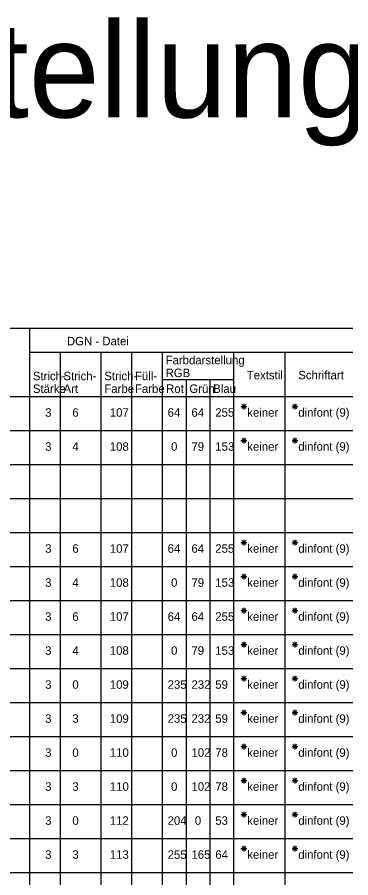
# Model space of a CAD drawing. Extents: x -14.3 to 23.8, y -56.3 to 8.
# Drawn here: x 11.07 to 15.97, y -8.08 to 4.57 of the extents above; entities that cross this region are included whole.
import ezdxf

# ---------------------------------------------------------------- set-up
doc = ezdxf.new("R2010")
doc.units = 0
doc.layers.add('Default', color=7, linetype='Continuous')

msp = doc.modelspace()

# ---------------------------------------------------------------- linework, layer by layer
at = {"layer": 'Default'}
for p, q in [((0, 0), (16, 0)), ((11.25, 0), (11.25, -53.5)), ((11.25, -0.35), (16, -0.35)), ((11.7, -0.35), (11.7, -44.5)), ((12.3, -0.35), (12.3, -44.5)), ((12.75, -0.35), (12.75, -44.5)), ((13.2, -0.35), (13.2, -44.5)), ((14.25, -0.35), (14.25, -48)), ((15, -0.35), (15, -48)), ((13.2, -0.75), (14.25, -0.75)), ((13.55, -0.75), (13.55, -44.5)), ((13.9, -0.75), (13.9, -44.5)), ((0, -1), (14.169, -1)), ((0, -1), (16, -1)), ((14.37, -1.12), (14.43, -1.18)), ((14.43, -1.12), (14.37, -1.18)), ((14.4, -1.108), (14.4, -1.192)), ((15.12, -1.12), (15.18, -1.18)), ((15.18, -1.12), (15.12, -1.18)), ((15.15, -1.108), (15.15, -1.192)), ((14.358, -1.15), (14.442, -1.15)), ((15.108, -1.15), (15.192, -1.15)), ((0, -1.5), (16, -1.5)), ((14.37, -1.62), (14.43, -1.68)), ((14.43, -1.62), (14.37, -1.68)), ((14.4, -1.608), (14.4, -1.692)), ((15.12, -1.62), (15.18, -1.68)), ((15.18, -1.62), (15.12, -1.68)), ((15.15, -1.608), (15.15, -1.692)), ((14.358, -1.65), (14.442, -1.65)), ((15.108, -1.65), (15.192, -1.65)), ((0, -2), (16, -2)), ((0, -2.5), (16, -2.5)), ((0, -3), (16, -3)), ((14.358, -3.15), (14.442, -3.15)), ((14.37, -3.12), (14.43, -3.18)), ((14.43, -3.12), (14.37, -3.18)), ((14.4, -3.108), (14.4, -3.192)), ((15.108, -3.15), (15.192, -3.15)), ((15.12, -3.12), (15.18, -3.18)), ((15.18, -3.12), (15.12, -3.18)), ((15.15, -3.108), (15.15, -3.192)), ((0, -3.5), (16, -3.5)), ((14.358, -3.65), (14.442, -3.65)), ((14.37, -3.62), (14.43, -3.68)), ((14.43, -3.62), (14.37, -3.68)), ((14.4, -3.608), (14.4, -3.692)), ((15.108, -3.65), (15.192, -3.65)), ((15.12, -3.62), (15.18, -3.68)), ((15.18, -3.62), (15.12, -3.68)), ((15.15, -3.608), (15.15, -3.692)), ((0, -4), (16, -4)), ((14.358, -4.15), (14.442, -4.15)), ((14.37, -4.12), (14.43, -4.18)), ((14.43, -4.12), (14.37, -4.18)), ((14.4, -4.108), (14.4, -4.192)), ((15.108, -4.15), (15.192, -4.15)), ((15.12, -4.12), (15.18, -4.18)), ((15.18, -4.12), (15.12, -4.18)), ((15.15, -4.108), (15.15, -4.192)), ((0, -4.5), (16, -4.5)), ((14.358, -4.65), (14.442, -4.65)), ((14.37, -4.62), (14.43, -4.68)), ((14.43, -4.62), (14.37, -4.68)), ((14.4, -4.608), (14.4, -4.692)), ((15.108, -4.65), (15.192, -4.65)), ((15.12, -4.62), (15.18, -4.68)), ((15.18, -4.62), (15.12, -4.68)), ((15.15, -4.608), (15.15, -4.692)), ((0, -5), (16, -5)), ((14.358, -5.15), (14.442, -5.15)), ((14.37, -5.12), (14.43, -5.18)), ((14.43, -5.12), (14.37, -5.18)), ((14.4, -5.108), (14.4, -5.192)), ((15.108, -5.15), (15.192, -5.15)), ((15.12, -5.12), (15.18, -5.18)), ((15.18, -5.12), (15.12, -5.18)), ((15.15, -5.108), (15.15, -5.192)), ((0, -5.5), (16, -5.5)), ((14.358, -5.65), (14.442, -5.65)), ((14.37, -5.62), (14.43, -5.68)), ((14.43, -5.62), (14.37, -5.68)), ((14.4, -5.608), (14.4, -5.692)), ((15.108, -5.65), (15.192, -5.65)), ((15.12, -5.62), (15.18, -5.68)), ((15.18, -5.62), (15.12, -5.68)), ((15.15, -5.608), (15.15, -5.692)), ((0, -6), (16, -6)), ((14.358, -6.15), (14.442, -6.15)), ((14.37, -6.12), (14.43, -6.18)), ((14.43, -6.12), (14.37, -6.18)), ((14.4, -6.108), (14.4, -6.192)), ((15.108, -6.15), (15.192, -6.15)), ((15.12, -6.12), (15.18, -6.18)), ((15.18, -6.12), (15.12, -6.18)), ((15.15, -6.108), (15.15, -6.192)), ((0, -6.5), (16, -6.5)), ((14.358, -6.65), (14.442, -6.65)), ((14.37, -6.62), (14.43, -6.68)), ((14.43, -6.62), (14.37, -6.68)), ((14.4, -6.608), (14.4, -6.692)), ((15.108, -6.65), (15.192, -6.65)), ((15.12, -6.62), (15.18, -6.68)), ((15.18, -6.62), (15.12, -6.68)), ((15.15, -6.608), (15.15, -6.692)), ((0, -7), (16, -7)), ((14.358, -7.15), (14.442, -7.15)), ((14.37, -7.12), (14.43, -7.18)), ((14.43, -7.12), (14.37, -7.18)), ((14.4, -7.108), (14.4, -7.192)), ((15.108, -7.15), (15.192, -7.15)), ((15.12, -7.12), (15.18, -7.18)), ((15.18, -7.12), (15.12, -7.18)), ((15.15, -7.108), (15.15, -7.192)), ((0, -7.5), (16, -7.5)), ((14.358, -7.65), (14.442, -7.65)), ((14.37, -7.62), (14.43, -7.68)), ((14.43, -7.62), (14.37, -7.68)), ((14.4, -7.608), (14.4, -7.692)), ((15.108, -7.65), (15.192, -7.65)), ((15.12, -7.62), (15.18, -7.68)), ((15.18, -7.62), (15.12, -7.68)), ((15.15, -7.608), (15.15, -7.692)), ((0, -8), (16, -8))]:
    msp.add_line(p, q, dxfattribs=at)

# ---------------------------------------------------------------- texts
for s, height, p in [('Leitungsdarstellung: Kälte ', 1.4, (0, 3.1)), ('DGN - Datei', 0.125, (11.8, -0.25)), ('Farbdarstellung', 0.125, (13.25, -0.529)), ('Strich-', 0.125, (11.3, -0.763)), ('Strich-', 0.125, (11.75, -0.763)), ('Strich-', 0.125, (12.35, -0.763)), ('Füll-', 0.125, (12.8, -0.763)), ('RGB', 0.125, (13.25, -0.717)), ('Textstil', 0.125, (14.443, -0.75)), ('Schriftart', 0.125, (15.2, -0.75)), ('Stärke', 0.125, (11.3, -0.95)), ('Art', 0.125, (11.75, -0.95)), ('Farbe', 0.125, (12.35, -0.95)), ('Farbe', 0.125, (12.8, -0.95)), ('Rot', 0.125, (13.258, -0.95)), ('Grün', 0.125, (13.6, -0.95)), ('Blau', 0.125, (13.95, -0.95)), ('3', 0.125, (11.48, -1.3)), ('6', 0.125, (11.88, -1.3)), ('107', 0.125, (12.43, -1.3)), ('64', 0.125, (13.28, -1.3)), ('64', 0.125, (13.63, -1.3)), ('255', 0.125, (13.98, -1.3)), ('keiner', 0.125, (14.45, -1.3)), ('dinfont (9)', 0.125, (15.2, -1.3)), ('3', 0.125, (11.48, -1.8)), ('4', 0.125, (11.88, -1.8)), ('108', 0.125, (12.43, -1.8)), ('0', 0.125, (13.33, -1.8)), ('79', 0.125, (13.63, -1.8)), ('153', 0.125, (13.98, -1.8)), ('keiner', 0.125, (14.45, -1.8)), ('dinfont (9)', 0.125, (15.2, -1.8)), ('3', 0.125, (11.48, -3.3)), ('6', 0.125, (11.88, -3.3)), ('107', 0.125, (12.43, -3.3)), ('64', 0.125, (13.28, -3.3)), ('64', 0.125, (13.63, -3.3)), ('255', 0.125, (13.98, -3.3)), ('keiner', 0.125, (14.45, -3.3)), ('dinfont (9)', 0.125, (15.2, -3.3)), ('keiner', 0.125, (14.45, -3.8)), ('dinfont (9)', 0.125, (15.2, -3.8)), ('3', 0.125, (11.48, -3.8)), ('4', 0.125, (11.88, -3.8)), ('108', 0.125, (12.43, -3.8)), ('0', 0.125, (13.33, -3.8)), ('79', 0.125, (13.63, -3.8)), ('153', 0.125, (13.98, -3.8)), ('3', 0.125, (11.48, -4.3)), ('6', 0.125, (11.88, -4.3)), ('107', 0.125, (12.43, -4.3)), ('64', 0.125, (13.28, -4.3)), ('64', 0.125, (13.63, -4.3)), ('255', 0.125, (13.98, -4.3)), ('keiner', 0.125, (14.45, -4.3)), ('dinfont (9)', 0.125, (15.2, -4.3)), ('3', 0.125, (11.48, -4.8)), ('4', 0.125, (11.88, -4.8)), ('108', 0.125, (12.43, -4.8)), ('0', 0.125, (13.33, -4.8)), ('79', 0.125, (13.63, -4.8)), ('153', 0.125, (13.98, -4.8)), ('keiner', 0.125, (14.45, -4.8)), ('dinfont (9)', 0.125, (15.2, -4.8)), ('3', 0.125, (11.48, -5.3)), ('0', 0.125, (11.88, -5.3)), ('109', 0.125, (12.43, -5.3)), ('235', 0.125, (13.28, -5.3)), ('232', 0.125, (13.63, -5.3)), ('59', 0.125, (13.98, -5.3)), ('keiner', 0.125, (14.45, -5.3)), ('dinfont (9)', 0.125, (15.2, -5.3)), ('3', 0.125, (11.48, -5.8)), ('3', 0.125, (11.88, -5.8)), ('109', 0.125, (12.43, -5.8)), ('235', 0.125, (13.28, -5.8)), ('232', 0.125, (13.63, -5.8)), ('59', 0.125, (13.98, -5.8)), ('keiner', 0.125, (14.45, -5.8)), ('dinfont (9)', 0.125, (15.2, -5.8)), ('3', 0.125, (11.48, -6.3)), ('0', 0.125, (11.88, -6.3)), ('110', 0.125, (12.43, -6.3)), ('0', 0.125, (13.33, -6.3)), ('102', 0.125, (13.63, -6.3)), ('78', 0.125, (13.98, -6.3)), ('keiner', 0.125, (14.45, -6.3)), ('dinfont (9)', 0.125, (15.2, -6.3)), ('3', 0.125, (11.48, -6.8)), ('3', 0.125, (11.88, -6.8)), ('110', 0.125, (12.43, -6.8)), ('0', 0.125, (13.33, -6.8)), ('102', 0.125, (13.63, -6.8)), ('78', 0.125, (13.98, -6.8)), ('keiner', 0.125, (14.45, -6.8)), ('dinfont (9)', 0.125, (15.2, -6.8)), ('3', 0.125, (11.48, -7.3)), ('0', 0.125, (11.88, -7.3)), ('112', 0.125, (12.43, -7.3)), ('204', 0.125, (13.28, -7.3)), ('0', 0.125, (13.68, -7.3)), ('53', 0.125, (13.98, -7.3)), ('keiner', 0.125, (14.45, -7.3)), ('dinfont (9)', 0.125, (15.2, -7.3)), ('3', 0.125, (11.48, -7.8)), ('3', 0.125, (11.88, -7.8)), ('113', 0.125, (12.43, -7.8)), ('255', 0.125, (13.28, -7.8)), ('165', 0.125, (13.63, -7.8)), ('64', 0.125, (13.98, -7.8)), ('keiner', 0.125, (14.45, -7.8)), ('dinfont (9)', 0.125, (15.2, -7.8))]:
    msp.add_text(s, height=height, dxfattribs=at).set_placement(p)

doc.saveas('drawing.dxf')
